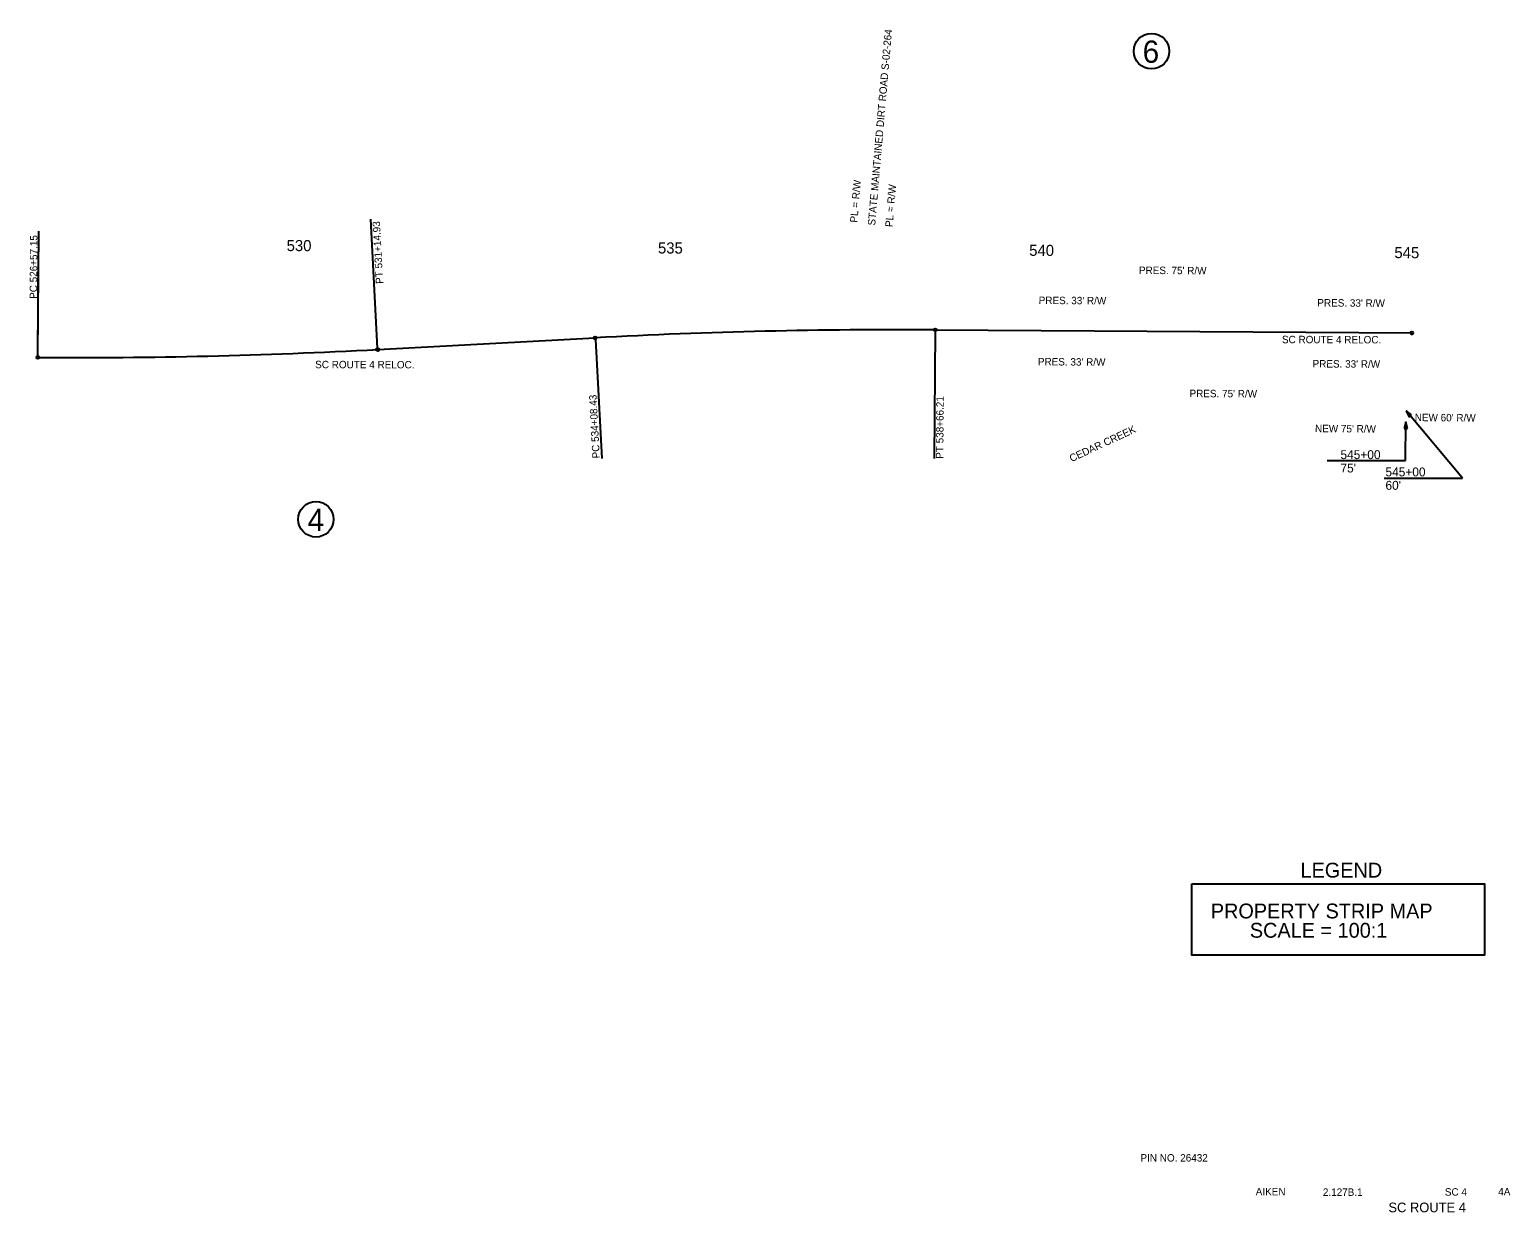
# Model space of a CAD drawing. Extents: x -64038 to -60878, y 1838 to 8465.
# Drawn here: x -62886 to -60892, y 3788 to 5381 of the extents above; entities that cross this region are included whole.
import ezdxf

# ---------------------------------------------------------------- set-up
doc = ezdxf.new("R2010")
doc.units = 0
for name, color, linetype in [('Level 1', 7, 'Continuous'), ('Level 13', 7, 'Continuous'), ('Level 19', 7, 'Continuous'), ('Level 21', 7, 'Continuous'), ('Level 24', 7, 'Continuous'), ('Level 25', 7, 'Continuous'), ('Level 33', 7, 'Continuous')]:
    doc.layers.add(name, color=color, linetype=linetype)

msp = doc.modelspace()

# ---------------------------------------------------------------- linework, layer by layer
at = {"layer": 'Level 1'}
msp.add_lwpolyline([(-61321.2, 4230.5), (-60927.4, 4230.5), (-60927.4, 4134.3), (-61321.2, 4134.3)], close=True, dxfattribs=at)
at = {"layer": 'Level 19'}
for p, q in [((-62417.8, 4952.1), (-62427.1, 5125.7)), ((-62875.3, 4941.4), (-62874.2, 5109.7)), ((-62875.3, 4941), (-62874.4, 5082.3)), ((-62417.7, 4950.1), (-62124.7, 4965.8)), ((-61667.1, 4974.6), (-61668.2, 4803.4)), ((-61667.1, 4976.6), (-61025.1, 4972.5)), ((-62124.6, 4963.8), (-62116, 4803.5))]:
    msp.add_line(p, q, dxfattribs=at)
for centre in [(-62124.7, 4965.8), (-61667.1, 4976.6), (-61025.1, 4972.5), (-62417.7, 4950.1), (-62875.3, 4939.4)]:
    msp.add_circle(centre, 2, dxfattribs=at)
for centre, start, end in [((-61716, -2662.8), 89.63338, 93.06665), ((-62826.4, 12578.8), 269.63337, 273.06663)]:
    msp.add_arc(centre, 7639.6, start, end, dxfattribs=at)
at = {"layer": 'Level 24'}
for p, q in [((-61032.9, 4867.6), (-61028.8, 4859.2)), ((-61025.4, 4862.1), (-61032.9, 4867.6)), ((-61033, 4852.6), (-61035.4, 4843.6)), ((-61030.9, 4843.5), (-61033, 4852.6)), ((-61028.8, 4859.2), (-61025.4, 4862.1)), ((-61035.4, 4843.6), (-61030.9, 4843.5))]:
    msp.add_line(p, q, dxfattribs=at)
at = {"layer": 'Level 25'}
for centre in [(-61375.7, 5352), (-62500.9, 4721.4)]:
    msp.add_circle(centre, 23.9, dxfattribs=at)
at = {"layer": 'Level 33'}
for p, q in [((-60956.8, 4777), (-61032.9, 4867.6)), ((-61033.6, 4800.4), (-61033, 4852.6)), ((-61139, 4800.4), (-61033.6, 4800.4)), ((-61062.2, 4777), (-60956.8, 4777))]:
    msp.add_line(p, q, dxfattribs=at)

# ---------------------------------------------------------------- texts
at = {"layer": 'Level 1'}
msp.add_text('CEDAR CREEK', height=10, rotation=24.993, dxfattribs=at).set_placement((-61483.3, 4798.3))
for s, height, p in [('LEGEND', 20, (-61175, 4238.8)), ('PROPERTY STRIP MAP', 20, (-61295.8, 4183.8)), ('SCALE = 100:1', 20, (-61243.2, 4157.8)), ('PIN NO. 26432', 10, (-61390.5, 3856.3)), ('AIKEN', 10, (-61235.3, 3810.8)), (' 2.127B.1', 10, (-61148.6, 3810.1)), ('SC 4', 10, (-60980.6, 3810.4)), ('4A', 10, (-60908.7, 3810.8))]:
    msp.add_text(s, height=height, dxfattribs=at).set_placement(p)
at = {"layer": 'Level 13'}
for s, rotation, p in [("PRES. 75' R/W", 359.6333, (-61392.6, 5051.9)), ("PRES. 33' R/W", 359.6333, (-61527.6, 5011.4)), ("PRES. 33' R/W", 359.6333, (-61152.4, 5008.1)), ('SC ROUTE 4 RELOC.', 359.8979, (-61200, 4958.6)), ('SC ROUTE 4 RELOC.', 359.8979, (-62501.9, 4924.9)), ("PRES. 33' R/W", 359.6333, (-61528.7, 4928.8)), ("PRES. 33' R/W", 359.6333, (-61158.8, 4926)), ("PRES. 75' R/W", 359.6333, (-61324.5, 4886))]:
    msp.add_text(s, height=10, rotation=rotation, dxfattribs=at).set_placement(p)
msp.add_text('SC ROUTE 4', height=13, dxfattribs=at).set_placement((-61056.6, 3788))
at = {"layer": 'Level 19'}
for s, rotation, p in [('PT 531+14.93', 93.0666, (-62410.2, 5038.8)), ('PC 526+57.15', 89.6334, (-62876.4, 5018.3)), ('PC 534+08.43', 93.0667, (-62118.5, 4803.7)), ('PT 538+66.21', 89.6334, (-61656, 4802.9))]:
    msp.add_text(s, height=10, rotation=rotation, dxfattribs=at).set_placement(p)
at = {"layer": 'Level 21'}
for s, p in [('530', (-62540.4, 5082.7)), ('535', (-62040.3, 5079.5)), ('540', (-61540.4, 5076.3)), ('545', (-61048.6, 5073.2))]:
    msp.add_text(s, height=15, rotation=359.6333, dxfattribs=at).set_placement(p)
at = {"layer": 'Level 25'}
for s, rotation, p in [('STATE MAINTAINED DIRT ROAD S-02-264', 85.0581, (-61747.8, 5116.8)), ('PL = R/W', 85.0661, (-61771.8, 5120.7)), ('PL = R/W', 85.0661, (-61724.4, 5114.7))]:
    msp.add_text(s, height=10, rotation=rotation, dxfattribs=at).set_placement(p)
for s, p in [('6', (-61387.6, 5336.3)), ('4', (-62512.1, 4705.7))]:
    msp.add_text(s, height=30, dxfattribs=at).set_placement(p)
at = {"layer": 'Level 33'}
for s, p in [("NEW 75' R/W", (-61155.5, 4838.8)), ("NEW 60' R/W", (-61021.2, 4853.7))]:
    msp.add_text(s, height=10, rotation=359.5312, dxfattribs=at).set_placement(p)
for s, p in [('545+00', (-61121.2, 4802.5)), ("75'", (-61121.2, 4784.5)), ('545+00', (-61060.6, 4779.2)), ("60'", (-61060.6, 4761.2))]:
    msp.add_text(s, height=12, dxfattribs=at).set_placement(p)

doc.saveas('drawing.dxf')
